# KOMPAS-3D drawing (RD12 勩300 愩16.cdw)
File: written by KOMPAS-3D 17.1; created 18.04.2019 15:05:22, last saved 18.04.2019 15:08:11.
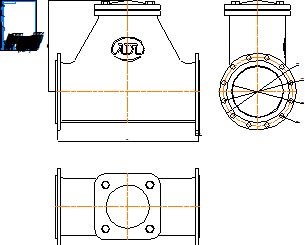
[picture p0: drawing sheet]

Sheet 1: A4, portrait

Title block, sheet 1: name: RD12 Ду300 Ру16; material: Внимание! Данный продукт является объектом авторского права ООО «Торговый Дом АДЛ». / Запрещается изменение, копирование, распространение / (в том числе путем копирования на другие сайты и ресурсы в Интернете) / или любое иное использование информации и объектов без предварительного / согласия правообладателя (ООО «Торговый Дом АДЛ»).; mass: 892,42; sheets: 1; organisation: ООО "Торговый дом АДЛ"; sheet format: A4

Views: Вид 1, Проекционный вид 2, Проекционный вид 3
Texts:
  user
Dimensions and other numbers on the sheet: 536,86; 17,5; 7; 836; 410; 455; 300; 28; 12 отв.; 1:1; 1; 892,42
